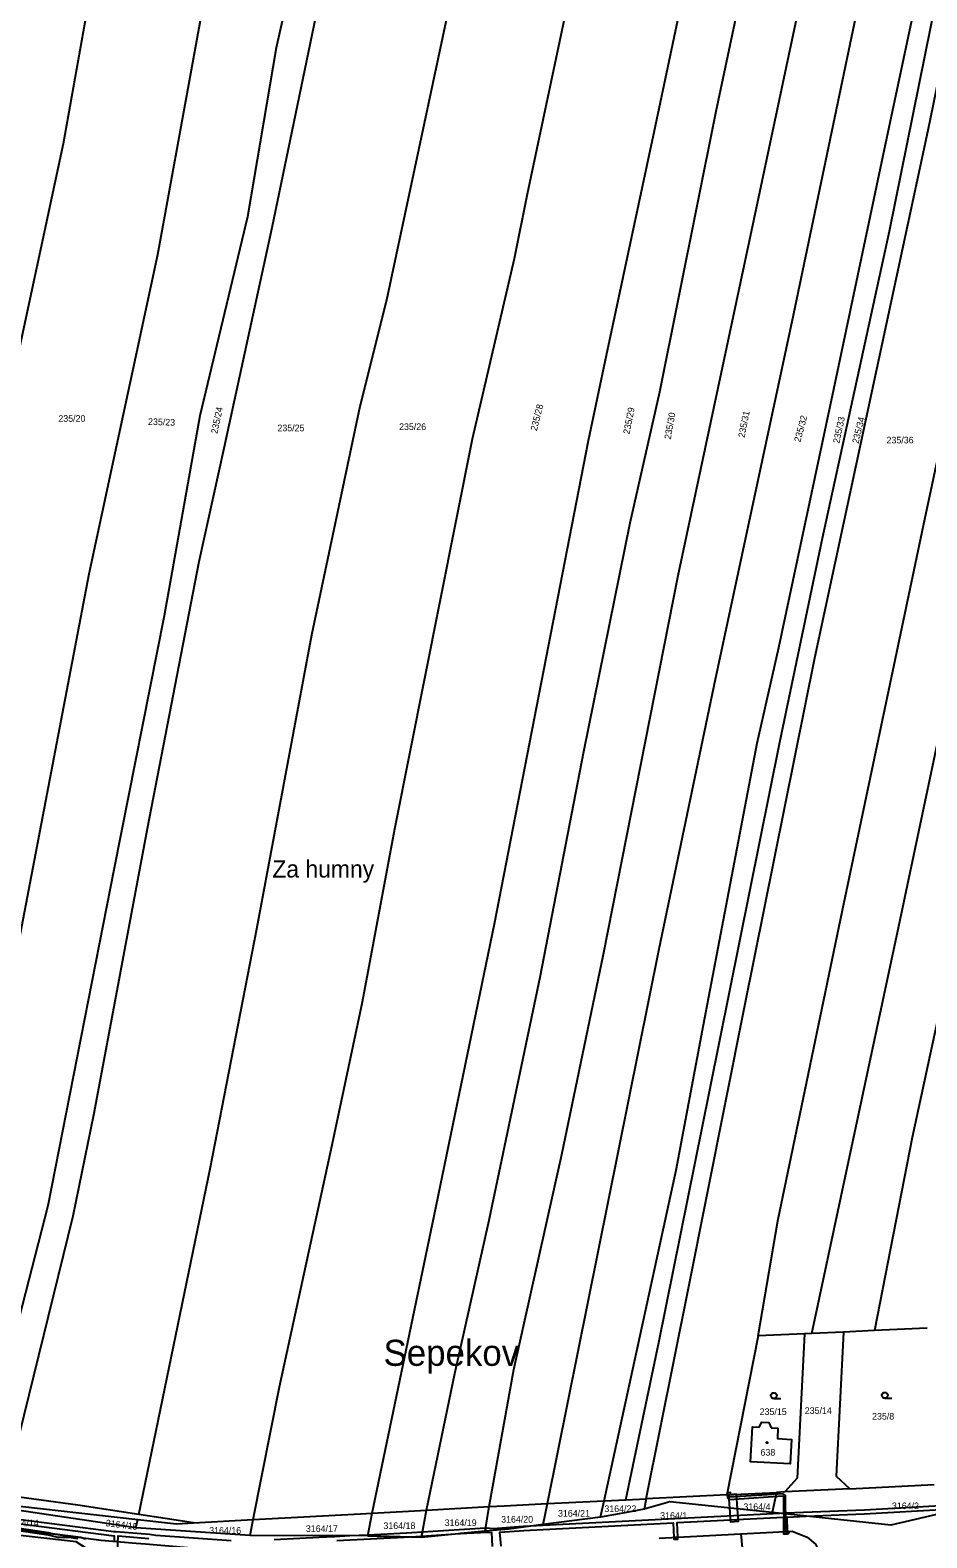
# Model space of a CAD drawing. Extents: x -776734 to -748832, y -1118122 to -976986.
# Drawn here: x -753275.1 to -753044.6, y -1115437.8 to -1115050.1 of the extents above; entities that cross this region are included whole.
import ezdxf

# ---------------------------------------------------------------- set-up
doc = ezdxf.new("R2010")
doc.units = 0
for name, color, linetype in [('KM_Hranice parcel', 7, 'Continuous'), ('KM_Parcelní čísla', 7, 'Continuous'), ('KM_Pop  PČ popisy', 7, 'Continuous'), ('KM_Věcná břemena k části', 7, 'Continuous'), ('KM_Značky budov', 7, 'Continuous'), ('KM_Značky kultur', 7, 'Continuous')]:
    doc.layers.add(name, color=color, linetype=linetype)

msp = doc.modelspace()

# ---------------------------------------------------------------- linework, layer by layer
at = {"layer": 'KM_Hranice parcel'}
for p, q in [((-753087.93, -1115385.88), (-753096, -1115426.75)), ((-753076, -1115385.34), (-753087.93, -1115385.88)), ((-753074.17, -1115385.26), (-753076, -1115385.34)), ((-753066.01, -1115384.89), (-753074.17, -1115385.26)), ((-753058.01, -1115384.53), (-753066.01, -1115384.89)), ((-753044.51, -1115383.92), (-753058.01, -1115384.53)), ((-753064.35, -1115425.19), (-753042.7, -1115424.12)), ((-753142.13, -1115429.02), (-753127.57, -1115428.31)), ((-753128.48, -1115432.49), (-753127.57, -1115428.31)), ((-753127.57, -1115428.31), (-753121.98, -1115428.03)), ((-753121.98, -1115428.03), (-753116.71, -1115427.77)), ((-753116.71, -1115427.77), (-753117.25, -1115430.43)), ((-753096, -1115426.75), (-753116.71, -1115427.77)), ((-753096, -1115426.75), (-753083.2, -1115426.12)), ((-753083.2, -1115426.12), (-753084.37, -1115431.34)), ((-753081.08, -1115426.01), (-753083.2, -1115426.12)), ((-753064.35, -1115425.19), (-753081.08, -1115426.01)), ((-753247.91, -1115435.28), (-753282.51, -1115430.07)), ((-753282.29, -1115429.17), (-753247.4, -1115433.1)), ((-753188.29, -1115437.34), (-753187.21, -1115431.46)), ((-753187.21, -1115431.46), (-753173.17, -1115430.68)), ((-753174.54, -1115437.76), (-753173.17, -1115430.68)), ((-753173.17, -1115430.68), (-753157.12, -1115429.79)), ((-753158.16, -1115436.1), (-753157.12, -1115429.79)), ((-753143.24, -1115434.39), (-753142.13, -1115429.02)), ((-753247.91, -1115435.28), (-753247.4, -1115433.1)), ((-753218.52, -1115437.23), (-753247.91, -1115435.28)), ((-753233.1, -1115433.98), (-753217.8, -1115433.14)), ((-753218.52, -1115437.23), (-753217.8, -1115433.14)), ((-753158.16, -1115436.1), (-753174.54, -1115437.76)), ((-753128.48, -1115432.49), (-753143.24, -1115434.39)), ((-753188.29, -1115437.34), (-753218.52, -1115437.23)), ((-753174.54, -1115437.76), (-753188.29, -1115437.34)), ((-753113.36, -1115437.88), (-753092.39, -1115436.81)), ((-753092.39, -1115436.81), (-753090.09, -1115460.62))]:
    msp.add_line(p, q, dxfattribs=at)
for points in [[(-753157.12, -1115429.79), (-753150.72, -1115394.51), (-753138.44, -1115339.24), (-753127.69, -1115287.77), (-753108.52, -1115190.37), (-753090.15, -1115104.28), (-753073.5, -1115025.89), (-753064.38, -1114979.16), (-753059.79, -1114955.29)], [(-753142.13, -1115429.02), (-753113.35, -1115286.36), (-753098.91, -1115217.03), (-753079.17, -1115125.01), (-753061.54, -1115040.52), (-753044.61, -1114954.39)], [(-753127.57, -1115428.31), (-753109.02, -1115343.31), (-753101.95, -1115305.88), (-753088.18, -1115233.5), (-753082.58, -1115208.88), (-753068.45, -1115142.47), (-753054.82, -1115077.88), (-753040.32, -1115009.27), (-753029.64, -1114954.22)], [(-753121.98, -1115428.03), (-753113.5, -1115387.63), (-753100.32, -1115322.58), (-753082.33, -1115233.25), (-753071.4, -1115180.79), (-753054.16, -1115101.79), (-753034.24, -1115003.46), (-753024.49, -1114954.16)], [(-753116.71, -1115427.77), (-753105.87, -1115373.64), (-753091.48, -1115301.38), (-753073.35, -1115211.52), (-753044.22, -1115075.89), (-753027.58, -1114994.65), (-753019.97, -1114954.11)], [(-753087.93, -1115385.88), (-753082.85, -1115356.32), (-753066.21, -1115276.38), (-753045.09, -1115175.92), (-753031.36, -1115111.65), (-753012.25, -1115017.92), (-752999.53, -1114954.05)], [(-753074.17, -1115385.26), (-753051.79, -1115280.52), (-753019.64, -1115128.38), (-752988.43, -1114977.02), (-752983.78, -1114954.34)], [(-753187.21, -1115431.46), (-753171.22, -1115354.98), (-753155.73, -1115279.97), (-753131.55, -1115155.67), (-753126.89, -1115133.75), (-753114.32, -1115074.76), (-753103.75, -1115024.73), (-753092.8, -1114975.75), (-753090.14, -1114959.41)], [(-753173.17, -1115430.68), (-753165.93, -1115395.55), (-753157.07, -1115356.14), (-753143.95, -1115293.66), (-753132.77, -1115235.62), (-753120.85, -1115176.85), (-753113.19, -1115143.15), (-753098.74, -1115070.99), (-753088.53, -1115022.81), (-753075.3, -1114957.32)], [(-752969, -1114956.89), (-752973.99, -1114979.61), (-752981.76, -1115020.52), (-753009.84, -1115157.88), (-753021.45, -1115211.53), (-753030.12, -1115252.85), (-753038.41, -1115288.88), (-753048.31, -1115334.89), (-753058.01, -1115384.53)], [(-753217.8, -1115433.14), (-753211.03, -1115398.97), (-753197.49, -1115336.74), (-753189.65, -1115300.03), (-753181.32, -1115255.47), (-753169.71, -1115196.97), (-753161.38, -1115155.22), (-753150.59, -1115108.84), (-753147.28, -1115092.2), (-753135.87, -1115038.32), (-753120.85, -1114968.78)], [(-753337.09, -1115412.19), (-753331.62, -1115395.18), (-753319.53, -1115340.8), (-753312.98, -1115305.64), (-753296.9, -1115224.92), (-753280.25, -1115143.21), (-753266.59, -1115079.29), (-753255.81, -1115019.21), (-753246.42, -1114978.13)], [(-753308.1, -1115421.53), (-753299.05, -1115385.38), (-753292.72, -1115360.89), (-753274.02, -1115263.55), (-753259.94, -1115189.91), (-753242.27, -1115107.78), (-753230.26, -1115041.93), (-753222.65, -1115005.26), (-753215.61, -1114976.64)], [(-753289.44, -1115425.79), (-753270.46, -1115352.32), (-753253.52, -1115265.95), (-753240.58, -1115200.65), (-753231.39, -1115149.23), (-753219.16, -1115098.09), (-753211.82, -1115054.59), (-753201.24, -1115007.6), (-753192.84, -1114975.54)], [(-753281.72, -1115426.85), (-753264.05, -1115355.01), (-753258.69, -1115328.65), (-753244.96, -1115255.46), (-753231.63, -1115186.8), (-753225.21, -1115157.64), (-753212.92, -1115100.88), (-753197.88, -1115028.53)], [(-753247.14, -1115431.84), (-753228.76, -1115342.49), (-753216.87, -1115281.25), (-753202.68, -1115205.58), (-753190.3, -1115146.78), (-753183.41, -1115119.5), (-753165.42, -1115034.99)], [(-753076, -1115385.34), (-753077.89, -1115422.5), (-753081.08, -1115426.01)], [(-753066.01, -1115384.89), (-753067.85, -1115422), (-753064.35, -1115425.19)], [(-753084.59, -1115409.5), (-753082.87, -1115409.6), (-753083, -1115412.31), (-753079.39, -1115412.5), (-753079.72, -1115418.78), (-753089.89, -1115418.25), (-753089.43, -1115409.27), (-753087.71, -1115409.35), (-753086.95, -1115408.08), (-753085.18, -1115408.14), (-753084.59, -1115409.5)], [(-752975.49, -1115424.57), (-753012.45, -1115428.99), (-753038.75, -1115431.04), (-753053.83, -1115434.58), (-753084.37, -1115431.34)], [(-753247.14, -1115431.84), (-753262.9, -1115429.43), (-753281.72, -1115426.85)], [(-753084.37, -1115431.34), (-753110.65, -1115428.56), (-753117.25, -1115430.43)], [(-753233.1, -1115433.98), (-753240.44, -1115432.86), (-753247.14, -1115431.84)], [(-753217.8, -1115433.14), (-753190.19, -1115431.62), (-753187.21, -1115431.46)], [(-753157.12, -1115429.79), (-753153.24, -1115429.57), (-753142.13, -1115429.02)], [(-753117.25, -1115430.43), (-753122.76, -1115431.51), (-753128.48, -1115432.49)], [(-753287.78, -1115434.4), (-753256.83, -1115438.41), (-753247.86, -1115439.17), (-753245.5, -1115439.38), (-753206.71, -1115442.68)], [(-753256.74, -1115452.88), (-753256.92, -1115446.38), (-753257.82, -1115442.69), (-753259.16, -1115441.5), (-753263.33, -1115438.86), (-753287.57, -1115436.12)], [(-753247.4, -1115433.1), (-753237.52, -1115434.22), (-753233.1, -1115433.98)], [(-753143.24, -1115434.39), (-753152, -1115435.58), (-753158.16, -1115436.1)], [(-753092.39, -1115436.81), (-753079.2, -1115436.14), (-753075.33, -1115437.62), (-753073.2, -1115439.48), (-753071.95, -1115441.84), (-753071.8, -1115442.63)]]:
    msp.add_lwpolyline(points, dxfattribs=at)
at = {"layer": 'KM_Věcná břemena k části'}
for points in [[(-753095.37, -1115426.72), (-753095, -1115426.7), (-753095.03, -1115426.2), (-753095.9, -1115426.24), (-753096, -1115426.75), (-753095.87, -1115426.74)], [(-753095.18, -1115427.4), (-753095.34, -1115427.29), (-753095.37, -1115426.72), (-753095.87, -1115426.74), (-753095.82, -1115427.57), (-753095.32, -1115427.92), (-753081.63, -1115427.05), (-753081.44, -1115427.19), (-753081.3, -1115435), (-753081.12, -1115436), (-753080.31, -1115436.76), (-753079.97, -1115436.4), (-753080.66, -1115435.74), (-753080.8, -1115434.96), (-753080.94, -1115426.93), (-753081.49, -1115426.53)], [(-753093.52, -1115426.63), (-753095.56, -1115426.73), (-753095.29, -1115430.18), (-753095.02, -1115433.69), (-753092.99, -1115433.53), (-753093.23, -1115430.4)], [(-753188.24, -1115437.09), (-753188.29, -1115437.34), (-753178.96, -1115437.63), (-753174.46, -1115437.35), (-753174.27, -1115436.34), (-753178.34, -1115436.59)], [(-753174.27, -1115436.34), (-753174.46, -1115437.35), (-753164.49, -1115436.74), (-753158.16, -1115436.1), (-753158.04, -1115435.35)], [(-753109.61, -1115437.69), (-753109.59, -1115438.19), (-753108.59, -1115438.14), (-753108.61, -1115437.64)]]:
    msp.add_lwpolyline(points, close=True, dxfattribs=at)
for points in [[(-753039.47, -1115429.48), (-753060.63, -1115430.68), (-753080.76, -1115431.48), (-753082.32, -1115431.56), (-753109.32, -1115432.9), (-753146.63, -1115434.85), (-753148.34, -1115434.94), (-753156.06, -1115435.47), (-753157.61, -1115435.32), (-753158.04, -1115435.35), (-753158.16, -1115436.1), (-753164.49, -1115436.74), (-753157.63, -1115436.32), (-753156.54, -1115436.43), (-753156.29, -1115440.08)], [(-753154.04, -1115439.97), (-753154.33, -1115436.36), (-753148.22, -1115435.94), (-753109.78, -1115433.93), (-753109.61, -1115437.69), (-753108.61, -1115437.64), (-753108.78, -1115433.87), (-753081.46, -1115432.52), (-753081.43, -1115436.25), (-753081.43, -1115436.82), (-753080.43, -1115436.81), (-753080.43, -1115436.2), (-753080.46, -1115432.47), (-753075.56, -1115432.27), (-753060.65, -1115431.68), (-753039.36, -1115430.48)], [(-753283, -1115433.53), (-753253.5, -1115437.29), (-753253.56, -1115438.69)], [(-753223.47, -1115438.63), (-753242.83, -1115437.23), (-753244.46, -1115436.96), (-753252.97, -1115436.25), (-753253.65, -1115436.27), (-753282.88, -1115432.54)], [(-753281.44, -1115435.43), (-753273.88, -1115436.54), (-753270.51, -1115437.03), (-753268.07, -1115437.64), (-753265.17, -1115437.66), (-753262.83, -1115437.99)], [(-753260.88, -1115438.16), (-753262.09, -1115437.73), (-753269.47, -1115436.77), (-753270.41, -1115436.53), (-753273.8, -1115436.04), (-753281.38, -1115434.93)], [(-753252.67, -1115441.35), (-753252.49, -1115437.29), (-753244.58, -1115437.95)], [(-753196.25, -1115438.5), (-753178.96, -1115437.63), (-753188.29, -1115437.34), (-753188.24, -1115437.09), (-753192.9, -1115437.32), (-753196.81, -1115437.52), (-753200.8, -1115437.73), (-753212.4, -1115438.35)]]:
    msp.add_lwpolyline(points, dxfattribs=at)
at = {"layer": 'KM_Značky budov'}
msp.add_circle((-753085.6268, -1115413.3192), 0.175, dxfattribs=at)
at = {"layer": 'KM_Značky kultur'}
for p, q in [((-753083.893, -1115402.01), (-753082.143, -1115402.01)), ((-753055.353, -1115401.92), (-753053.603, -1115401.92))]:
    msp.add_line(p, q, dxfattribs=at)
for centre in [(-753083.8929, -1115401.2598), (-753055.3529, -1115401.1698)]:
    msp.add_circle(centre, 0.75, dxfattribs=at)

# ---------------------------------------------------------------- texts
at = {"layer": 'KM_Parcelní čísla'}
for s, p in [('235/20', (-753267.87, -1115150.84)), ('235/25', (-753211.54, -1115153.27)), ('235/26', (-753180.26, -1115152.95)), ('235/36', (-753054.92, -1115156.4)), ('235/15', (-753087.55, -1115406.23)), ('235/14', (-753075.95, -1115405.95)), ('235/8', (-753058.64, -1115407.41)), ('638', (-753087.33, -1115416.68)), ('3164/20', (-753154.02, -1115433.91)), ('3164/21', (-753139.4, -1115432.36)), ('3164/22', (-753127.476, -1115431.19)), ('3164/1', (-753113.13, -1115432.93)), ('3164/4', (-753091.72, -1115430.68)), ('3164/2', (-753053.54, -1115430.44)), ('3164/14', (-753281.14, -1115434.818)), ('3164/16', (-753229.09, -1115436.77)), ('3164/17', (-753204.22, -1115436.29)), ('3164/18', (-753184.29, -1115435.55)), ('3164/19', (-753168.54, -1115434.78))]:
    msp.add_text(s, height=1.7, dxfattribs=at).set_placement(p)
for s, rotation, p in [('235/24', 78, (-753226.998, -1115154.026)), ('235/28', 76, (-753144.855, -1115153.305)), ('235/29', 79, (-753121.005, -1115154.142)), ('235/30', 80, (-753110.402, -1115155.447)), ('235/31', 79, (-753091.425, -1115155.032)), ('235/32', 75, (-753077.098, -1115156.189)), ('235/23', 358, (-753244.829, -1115151.619)), ('235/33', 78, (-753067.058, -1115156.516)), ('235/34', 76, (-753062.155, -1115156.575)), ('3164/15', 353, (-753255.783, -1115434.803))]:
    msp.add_text(s, height=1.7, rotation=rotation, dxfattribs=at).set_placement(p)
at = {"layer": 'KM_Pop  PČ popisy'}
for s, height, p in [('Za humny', 4.4, (-753212.843, -1115268.02)), ('Sepekov', 6.7, (-753184.26, -1115393.59))]:
    msp.add_text(s, height=height, dxfattribs=at).set_placement(p)

doc.saveas('drawing.dxf')
